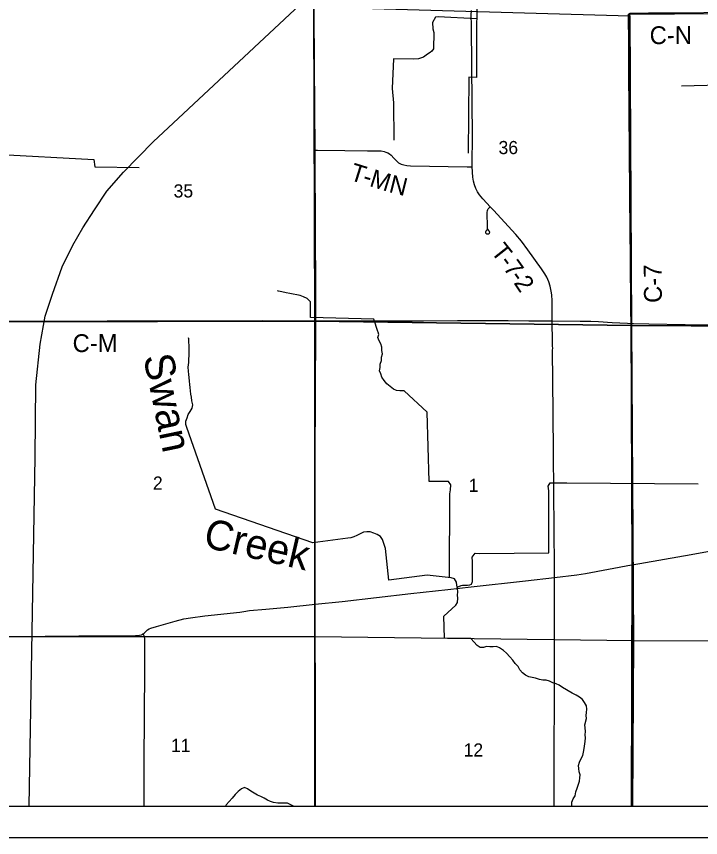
# Model space of a CAD drawing. Extents: x 0 to 34, y 0 to 22.
# Drawn here: x 5.564 to 7.743, y 14 to 16.618 of the extents above; entities that cross this region are included whole.
import ezdxf

# ---------------------------------------------------------------- set-up
doc = ezdxf.new("R2010")
doc.units = 0
for name, color, linetype in [('Default', 7, 'Continuous'), ('GM_X_County_Road', 7, 'Continuous'), ('GM_X_County_Road_Text', 7, 'Continuous'), ('GM_X_Minor_River', 7, 'Continuous'), ('GM_X_Minor_River_Text', 7, 'Continuous'), ('GM_X_Rail_Line', 7, 'Continuous'), ('GM_X_Section', 7, 'Continuous'), ('GM_X_Section_Text', 7, 'Continuous'), ('GM_X_Township_Road', 7, 'Continuous'), ('GM_X_Township_Road_Text', 7, 'Continuous'), ('SH_Cut_Line', 7, 'Continuous'), ('SH_Data', 7, 'Continuous')]:
    doc.layers.add(name, color=color, linetype=linetype)

msp = doc.modelspace()

# ---------------------------------------------------------------- linework, layer by layer
at = {"layer": 'Default'}
for points in [[(2.1, 16.6348), (2.1, 14.1), (7.5225, 14.1), (7.5244, 14.8701), (7.5216, 15.6399), (7.5206, 15.6813), (7.5192, 15.8554), (7.5184, 15.927), (7.5171, 16.0545), (7.5165, 16.1851), (7.5145, 16.4463), (7.5138, 16.5271), (7.5134, 16.6254)], [(7.8317, 16.6301), (7.6731, 16.6285), (7.5767, 16.6277), (7.5362, 16.6274), (7.5232, 16.6271), (7.5217, 16.6271), (7.5197, 16.6269), (7.5175, 16.6266), (7.5154, 16.6261), (7.5134, 16.6254), (7.5138, 16.5271), (7.5145, 16.4463), (7.5165, 16.1851), (7.5171, 16.0545), (7.5184, 15.927), (7.5192, 15.8554), (7.5206, 15.6813), (7.5216, 15.6399), (7.5244, 14.8701), (7.5225, 14.1), (8.9, 14.1)]]:
    msp.add_lwpolyline(points, dxfattribs=at)
for points in [[(5.5091, 14.1), (6.5139, 14.1), (6.5138, 14.6401), (5.5125, 14.6396)], [(6.5139, 14.1), (7.5259, 14.1), (7.529, 14.6277), (6.5138, 14.6401)], [(7.5259, 14.1), (8.6609, 14.1), (8.6655, 14.6229), (7.529, 14.6277)]]:
    msp.add_lwpolyline(points, close=True, dxfattribs=at)
at = {"layer": 'GM_X_County_Road'}
for points in [[(7.5219, 15.6393), (7.5208, 15.6808), (7.5195, 15.8549), (7.5186, 15.9264), (7.5174, 16.0539), (7.5167, 16.1845), (7.5147, 16.4457), (7.5141, 16.5265), (7.5136, 16.6249)], [(5.5139, 15.6462), (5.5634, 15.6462), (5.6256, 15.6465), (5.6629, 15.6464), (5.7531, 15.6465), (5.8526, 15.6468), (5.9178, 15.647), (6.1697, 15.6475), (6.2288, 15.6478), (6.3469, 15.6481), (6.4649, 15.6475), (6.5173, 15.6474)], [(6.5173, 15.6474), (6.5768, 15.6473), (6.7012, 15.6471), (6.7758, 15.6475), (6.8597, 15.6478), (6.9686, 15.6487), (7.0152, 15.6484), (7.0462, 15.6484), (7.1301, 15.6481), (7.1954, 15.6477), (7.2704, 15.6471)], [(7.2704, 15.6471), (7.3592, 15.6464), (7.3929, 15.6459), (7.4177, 15.645), (7.4611, 15.6424), (7.5098, 15.6398), (7.5219, 15.6393)], [(7.2772, 14.8294), (7.277, 14.8607), (7.2739, 15.2244), (7.2728, 15.3549), (7.2715, 15.5539), (7.2718, 15.5603), (7.2715, 15.5663), (7.2715, 15.5787), (7.2704, 15.6471)], [(7.5219, 15.6393), (7.5287, 15.6392), (7.5784, 15.6382), (7.6935, 15.6361), (7.7713, 15.6349), (7.8491, 15.6344), (7.9019, 15.6346), (7.9393, 15.6345), (7.9828, 15.6338), (8.0637, 15.633), (8.1228, 15.6321), (8.2161, 15.6312), (8.2458, 15.6312), (8.2489, 15.6311)], [(7.5247, 14.8696), (7.7126, 14.9025), (7.8471, 14.927), (7.8589, 14.9287), (7.8638, 14.929), (7.8685, 14.9287), (7.8729, 14.9281), (7.8779, 14.927), (7.8896, 14.9232), (7.9513, 14.9019), (8.0162, 14.8804), (8.1011, 14.8539)], [(7.2772, 14.8294), (7.3484, 14.8375), (7.3761, 14.8414), (7.5227, 14.8692), (7.5247, 14.8696)], [(6.5151, 14.7439), (6.6008, 14.7531), (6.8201, 14.7783), (6.9375, 14.7909), (7.0117, 14.7991), (7.1847, 14.8188), (7.2772, 14.8294)], [(7.2765, 14.1), (7.2762, 14.1844), (7.2762, 14.2092), (7.2763, 14.2683), (7.277, 14.4486), (7.2772, 14.548), (7.2774, 14.7861), (7.2772, 14.8294)], [(5.9667, 14.649), (5.9673, 14.6494), (5.9699, 14.6513), (5.9765, 14.658), (5.9811, 14.6619), (5.9862, 14.665), (5.9919, 14.6674), (6.0096, 14.6729), (6.0694, 14.6901), (6.0964, 14.697), (6.1178, 14.7008), (6.164, 14.7071), (6.2752, 14.7188), (6.2874, 14.7211), (6.3057, 14.7236), (6.3582, 14.7277), (6.4278, 14.7346), (6.5151, 14.7439)], [(5.5165, 14.641), (5.548, 14.6414), (5.7625, 14.643), (5.9428, 14.6444), (5.9553, 14.6451), (5.9616, 14.6465), (5.9645, 14.6477), (5.9667, 14.649)], [(5.9707, 14.1), (5.9705, 14.1367), (5.9704, 14.2113), (5.9718, 14.4166), (5.9723, 14.5068), (5.9729, 14.6032), (5.973, 14.6281), (5.9728, 14.6322), (5.9727, 14.6346), (5.9713, 14.6402), (5.9704, 14.6426), (5.9691, 14.6452), (5.9675, 14.6478), (5.9667, 14.649)]]:
    msp.add_lwpolyline(points, dxfattribs=at)
at = {"layer": 'GM_X_Minor_River'}
for points in [[(7.0297, 16.7897), (7.029, 16.4232), (7.0051, 16.4238), (7.0024, 16.1814)], [(7.0294, 16.6102), (6.9073, 16.6164), (6.8985, 16.6154), (6.8885, 16.5984), (6.8897, 16.5779), (6.893, 16.5668), (6.8917, 16.5141), (6.8867, 16.5066), (6.8817, 16.5024), (6.8733, 16.4972), (6.8607, 16.4875), (6.8439, 16.4827), (6.8276, 16.481), (6.7647, 16.482), (6.7602, 16.3879), (6.7646, 16.3423), (6.7659, 16.2232)], [(7.8449, 16.3991), (7.6819, 16.3958)], [(5.4958, 16.1786), (5.8099, 16.1617), (5.8134, 16.1382), (5.9544, 16.136)], [(6.5004, 15.7075), (6.4892, 15.7182), (6.4782, 15.7233), (6.4677, 15.7279), (6.4563, 15.7299), (6.4453, 15.7327), (6.4348, 15.7347), (6.423, 15.7367), (6.409, 15.7399), (6.3981, 15.7415), (6.395, 15.7427)], [(6.7147, 15.6135), (6.7018, 15.6524), (6.5006, 15.6574), (6.5004, 15.7075)], [(6.7986, 15.4237), (6.7846, 15.4246), (6.7743, 15.4255), (6.7642, 15.4298), (6.7536, 15.4375), (6.7431, 15.4467), (6.7345, 15.4566), (6.7274, 15.4677), (6.7241, 15.478), (6.7197, 15.4879), (6.7225, 15.4989), (6.7226, 15.5087), (6.7265, 15.5208), (6.7263, 15.5318), (6.7298, 15.5421), (6.728, 15.5523), (6.7274, 15.5637), (6.7245, 15.5736), (6.7185, 15.5835), (6.7148, 15.5942), (6.7176, 15.604), (6.7155, 15.611), (6.7147, 15.6135)], [(6.1066, 15.3077), (6.1033, 15.3172), (6.103, 15.3274), (6.1069, 15.3376), (6.1104, 15.3482), (6.1166, 15.358), (6.1228, 15.3694), (6.1252, 15.38), (6.1227, 15.3921), (6.1209, 15.4035), (6.1195, 15.4134), (6.1181, 15.4237), (6.1171, 15.4347), (6.1161, 15.4442), (6.1147, 15.4552), (6.1133, 15.4662), (6.1123, 15.4761), (6.1116, 15.4871), (6.1102, 15.5), (6.1127, 15.5148), (6.1128, 15.5254), (6.1137, 15.5368), (6.1134, 15.5474), (6.1136, 15.558), (6.1133, 15.5683), (6.1127, 15.5797), (6.1124, 15.5896), (6.1121, 15.5926)], [(6.9435, 14.8289), (6.9439, 15.0963), (6.9459, 15.1085), (6.9468, 15.1248), (6.9394, 15.1355), (6.9269, 15.1352), (6.8787, 15.1353), (6.8717, 15.3559), (6.7986, 15.4237)], [(6.6189, 14.9546), (6.508, 14.9394), (6.1976, 15.0472), (6.1066, 15.3077)], [(6.9678, 14.7986), (6.9804, 14.8031), (6.9849, 14.8049), (6.9921, 14.8045), (7.0005, 14.8044), (7.0077, 14.8054), (7.013, 14.8073), (7.0165, 14.816), (7.016, 14.8676), (7.0161, 14.8805), (7.0155, 14.8941), (7.0244, 14.9066), (7.0384, 14.9053), (7.2594, 14.9077), (7.2591, 15.078), (7.2596, 15.0909), (7.2594, 15.1054), (7.2576, 15.1198), (7.2638, 15.1311), (7.3168, 15.1308)], [(7.3168, 15.1308), (7.7355, 15.128)], [(6.7387, 14.9212), (6.7332, 14.9402), (6.7299, 14.9497), (6.7232, 14.9593), (6.7127, 14.9658), (6.7021, 14.9709), (6.6904, 14.9744), (6.6794, 14.9749), (6.6695, 14.9735), (6.6581, 14.9687), (6.6474, 14.9627), (6.6379, 14.9582), (6.6284, 14.9553), (6.6189, 14.9546)], [(6.9484, 14.8284), (6.8719, 14.836), (6.7501, 14.8205), (6.7387, 14.9212)], [(6.9633, 14.7408), (6.9682, 14.7493), (6.9697, 14.7637), (6.969, 14.7732), (6.9699, 14.7834), (6.9685, 14.7941), (6.9667, 14.8051), (6.9653, 14.8146), (6.959, 14.8253), (6.9484, 14.8284)], [(6.9251, 14.7061), (6.9633, 14.7408)], [(7.0107, 14.635), (6.9269, 14.6359), (6.9251, 14.7061)], [(7.3027, 14.4785), (7.2926, 14.4858), (7.2824, 14.4897), (7.2726, 14.4936), (7.2612, 14.499), (7.251, 14.5014), (7.2404, 14.5018), (7.2295, 14.5042), (7.217, 14.5078), (7.206, 14.5105), (7.1958, 14.5125), (7.1856, 14.5176), (7.1755, 14.5249), (7.1669, 14.5348), (7.1617, 14.5455), (7.1523, 14.5551), (7.1445, 14.5658), (7.1351, 14.5761), (7.125, 14.5876), (7.1149, 14.5964), (7.1021, 14.6045), (7.0923, 14.6096), (7.0817, 14.6085), (7.0714, 14.6082), (7.0612, 14.6087), (7.0513, 14.6058), (7.0411, 14.6063), (7.0313, 14.6128), (7.0107, 14.635)], [(7.3465, 14.4538), (7.3333, 14.4608), (7.3027, 14.4785)], [(7.3324, 14.1), (7.3326, 14.1129), (7.337, 14.1235), (7.3429, 14.1336), (7.3458, 14.1453), (7.3502, 14.1578), (7.3538, 14.1699), (7.3567, 14.18), (7.3584, 14.1903), (7.359, 14.1997), (7.3562, 14.2101), (7.3545, 14.2207), (7.3543, 14.2302), (7.3575, 14.2404), (7.3612, 14.2502), (7.3678, 14.2615), (7.3703, 14.2728), (7.3721, 14.2842), (7.3748, 14.3061), (7.3762, 14.3175), (7.3748, 14.3274), (7.3762, 14.3384), (7.3753, 14.3494), (7.374, 14.3593), (7.3789, 14.3797), (7.3787, 14.3892), (7.3793, 14.3987), (7.3803, 14.4097), (7.379, 14.4203), (7.3735, 14.4303), (7.3669, 14.4399), (7.3574, 14.4479), (7.3465, 14.4538)], [(6.446, 14.1), (6.4377, 14.1044), (6.4268, 14.11), (6.4166, 14.1094), (6.4064, 14.11), (6.3961, 14.1099), (6.3829, 14.1121), (6.3731, 14.115), (6.3633, 14.1197), (6.3525, 14.1253), (6.342, 14.1305), (6.3318, 14.1356), (6.3206, 14.1412), (6.3098, 14.1483), (6.2997, 14.1553), (6.2895, 14.1601), (6.28, 14.1558), (6.2699, 14.1473), (6.2605, 14.1368), (6.2512, 14.1257), (6.2414, 14.1149), (6.2321, 14.1044), (6.229, 14.1)]]:
    msp.add_lwpolyline(points, dxfattribs=at)
at = {"layer": 'GM_X_Rail_Line'}
msp.add_lwpolyline([(5.6036, 14.1), (5.6231, 15.2124), (5.6254, 15.4429), (5.6392, 15.5731), (5.6554, 15.6619), (5.6784, 15.7322), (5.7095, 15.8198), (5.7429, 15.8889), (5.7752, 15.9442), (5.8121, 16.0007), (5.8512, 16.0606), (5.9042, 16.1217), (5.9987, 16.2174), (6.5299, 16.7153), (7.3509, 17.4922), (8.0819, 18.1807), (8.7161, 18.7707), (8.9, 18.9438)], dxfattribs=at)
at = {"layer": 'GM_X_Section'}
for points in [[(5.5052, 16.6454), (6.5111, 16.648), (6.5138, 15.6467), (5.5125, 15.6443)], [(6.5111, 16.648), (7.5171, 16.6191), (7.5223, 15.6321), (6.5138, 15.6467)], [(7.5172, 16.6244), (8.6573, 16.6339), (8.6614, 15.6262), (7.5223, 15.6321), (7.5171, 16.6191)], [(5.5125, 15.6443), (6.5138, 15.6467), (6.5138, 14.6401), (5.5125, 14.6396)], [(6.5138, 15.6467), (7.5223, 15.6321), (7.529, 14.6277), (6.5138, 14.6401)], [(7.5223, 15.6321), (8.6614, 15.6262), (8.6655, 14.6229), (7.529, 14.6277)]]:
    msp.add_lwpolyline(points, close=True, dxfattribs=at)
at = {"layer": 'GM_X_Township_Road'}
msp.add_line((6.5151, 14.7209), (6.5151, 14.7439), dxfattribs=at)
for points in [[(6.5149, 16.1915), (6.5149, 16.1968), (6.5147, 16.2216), (6.5142, 16.2961), (6.5127, 16.4952), (6.5118, 16.6008), (6.5118, 16.6509)], [(7.0152, 16.1383), (7.0155, 16.1476), (7.0159, 16.2345), (7.0139, 16.4585), (7.0129, 16.5891), (7.0125, 16.6233), (7.0129, 16.6361)], [(6.5173, 15.6474), (6.5173, 15.6742), (6.5172, 15.7271), (6.5169, 15.7924), (6.5164, 15.8889), (6.5159, 15.9479), (6.515, 16.1626), (6.5149, 16.1915)], [(6.5149, 16.1915), (6.5227, 16.1914), (6.6099, 16.1904), (6.6815, 16.1897), (6.7127, 16.1894), (6.7252, 16.1887), (6.7345, 16.1872), (6.7406, 16.1852), (6.7464, 16.1826), (6.7518, 16.1793), (6.7567, 16.1753), (6.7653, 16.1661), (6.7737, 16.1571), (6.781, 16.1515), (6.789, 16.1472), (6.7978, 16.1444), (6.8069, 16.1428), (6.8192, 16.1419), (6.9996, 16.1382), (7.0152, 16.1383)], [(7.0727, 16.0107), (7.0617, 16.0229), (7.049, 16.0367), (7.0391, 16.0485), (7.0323, 16.0587), (7.0267, 16.0696), (7.0223, 16.0811), (7.0192, 16.093), (7.0176, 16.1052), (7.0152, 16.1383)], [(7.0642, 15.9391), (7.0675, 15.9353), (7.0684, 15.9344), (7.0692, 15.9333), (7.0697, 15.9325), (7.0702, 15.9312), (7.0703, 15.9299), (7.0702, 15.9285), (7.0698, 15.927), (7.0692, 15.9259), (7.0684, 15.9248), (7.0673, 15.924), (7.066, 15.9234), (7.0646, 15.9232), (7.0639, 15.9233), (7.0629, 15.9235), (7.0621, 15.9237), (7.0614, 15.9242), (7.0603, 15.9251), (7.0594, 15.9262), (7.0589, 15.9274), (7.0585, 15.9287), (7.0585, 15.9301), (7.0587, 15.9314), (7.0591, 15.9325), (7.0595, 15.9333), (7.06, 15.9341), (7.0607, 15.9349), (7.0613, 15.9357), (7.0625, 15.9369), (7.0632, 15.938), (7.0637, 15.9389), (7.064, 15.9399), (7.0641, 15.9408), (7.0644, 15.9427), (7.0643, 15.9458), (7.0633, 15.993), (7.0639, 15.9991), (7.0648, 16.0018), (7.0665, 16.0042), (7.0727, 16.0107)], [(7.2704, 15.6471), (7.2698, 15.6839), (7.2697, 15.711), (7.2689, 15.7297), (7.2672, 15.7421), (7.2638, 15.7573), (7.2589, 15.7721), (7.2526, 15.7865), (7.2466, 15.7974), (7.2359, 15.8127), (7.1926, 15.8735), (7.1724, 15.9011), (7.1544, 15.9225), (7.0832, 16.0003), (7.0727, 16.0107)], [(6.5151, 14.7439), (6.5151, 14.7475), (6.515, 14.8688), (6.5151, 14.8936), (6.5149, 14.9465), (6.5148, 15.0149), (6.5149, 15.0585), (6.5151, 15.1144), (6.5153, 15.2668), (6.5155, 15.2917), (6.5157, 15.3259), (6.516, 15.3788), (6.5164, 15.4503), (6.5172, 15.5903), (6.5173, 15.6369), (6.5173, 15.6474)], [(6.5158, 14.1), (6.5157, 14.3618), (6.5157, 14.4956), (6.5152, 14.62), (6.5146, 14.6628), (6.515, 14.7039), (6.5151, 14.7209)]]:
    msp.add_lwpolyline(points, dxfattribs=at)
at = {"layer": 'SH_Cut_Line'}
msp.add_lwpolyline([(2.1, 20.6957), (2.1, 14.1), (8.9, 14.1), (8.9, 20.8277), (8.6079, 20.8216), (7.476, 20.811), (6.4789, 20.8005), (5.4741, 20.7803), (4.4698, 20.7584), (3.7151, 20.7343), (2.4566, 20.7022)], close=True, dxfattribs=at)
at = {"layer": 'SH_Data'}
for p, q in [((2.1, 14.1), (8.9, 14.1)), ((2, 14), (9, 14))]:
    msp.add_line(p, q, dxfattribs=at)

# ---------------------------------------------------------------- texts
at = {"layer": 'GM_X_County_Road_Text'}
for s, rotation, p in [('C-N', 0.3977, (7.5807, 16.5292)), ('C-7', 90.4581, (7.6196, 15.7045)), ('C-M', 0.3636, (5.7426, 15.5475))]:
    msp.add_text(s, height=0.05682, rotation=rotation, dxfattribs=at).set_placement(p)
at = {"layer": 'GM_X_Minor_River_Text'}
for s, rotation, p in [('Swan', 281.6627, (5.9673, 15.5327)), ('Creek', 346.9803, (6.1551, 14.9272))]:
    msp.add_text(s, height=0.09476, rotation=rotation, dxfattribs=at).set_placement(p)
at = {"layer": 'GM_X_Section_Text'}
for s, height, p in [('36', 0.04186, (7.0992, 16.1788)), ('35', 0.04186, (6.0642, 16.0405)), ('2', 0.0419, (5.9983, 15.1091)), ('1', 0.0419, (7.0042, 15.1021)), ('11', 0.04186, (6.0558, 14.273)), ('12', 0.04186, (6.9879, 14.2583))]:
    msp.add_text(s, height=height, rotation=0, dxfattribs=at).set_placement(p)
at = {"layer": 'GM_X_Township_Road_Text'}
for s, rotation, p in [('T', 342.5734, (6.6223, 16.0972)), ('M', 342.7092, (6.6853, 16.0775)), ('-', 342.5936, (6.6629, 16.0845)), ('N', 345.8475, (6.7474, 16.0583)), ('T', 308.2997, (7.0729, 15.8671)), ('-', 306.1439, (7.0989, 15.8342)), ('7', 305.522, (7.1125, 15.8155)), ('2', 303.895, (7.1461, 15.7683)), ('-', 305.4115, (7.1328, 15.787))]:
    msp.add_text(s, height=0.0568, rotation=rotation, dxfattribs=at).set_placement(p)

doc.saveas('drawing.dxf')
